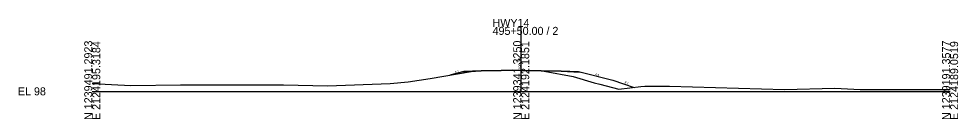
# Model space of a CAD drawing. Extents: x -26 to 303, y -10 to 11521.
# Drawn here: x -25.7 to 302.8, y 6990.3 to 7025.3 of the extents above; entities that cross this region are included whole.
import ezdxf

# ---------------------------------------------------------------- set-up
doc = ezdxf.new("R2010")
doc.units = 0
for name, color, linetype in [('XS_CELL', 7, 'Continuous'), ('XS_P_FINISHED_GRADE', 7, 'Continuous'), ('XS_P_SUBGRADE_GRANULAR', 7, 'Continuous'), ('XS_P_SUBGRADE_LEVELING', 7, 'Continuous'), ('XS_P_TX_FS_BS', 7, 'Continuous'), ('XS_X_GROUND', 7, 'Continuous'), ('XS_X_GROUND_TX', 7, 'Continuous')]:
    doc.layers.add(name, color=color, linetype=linetype)

msp = doc.modelspace()

# ---------------------------------------------------------------- linework, layer by layer
at = {"layer": 'XS_CELL'}
for p, q in [((150, 7000), (150, 7022.48)), ((0, 7000), (150, 7000)), ((150, 7000), (300, 7000))]:
    msp.add_line(p, q, dxfattribs=at)
at = {"layer": 'XS_P_FINISHED_GRADE'}
for p, q in [((130, 7006.87), (125.03, 7005.63)), ((136, 7007.11), (130, 7006.87)), ((150, 7007.39), (136, 7007.11)), ((150, 7007.39), (164, 7007.11)), ((164, 7007.11), (170, 7006.87)), ((170, 7006.87), (182, 7003.87)), ((182, 7003.87), (189.47, 7001.38))]:
    msp.add_line(p, q, dxfattribs=at)
at = {"layer": 'XS_P_SUBGRADE_GRANULAR'}
for p, q in [((136, 7006.99), (129.4, 7006.72)), ((164, 7006.99), (170.6, 7006.72))]:
    msp.add_line(p, q, dxfattribs=at)
at = {"layer": 'XS_P_SUBGRADE_LEVELING'}
for p, q in [((150, 7007.26), (136, 7006.99)), ((136, 7006.99), (136, 7007.11)), ((150, 7007.26), (164, 7006.99)), ((164, 7006.99), (164, 7007.11))]:
    msp.add_line(p, q, dxfattribs=at)
at = {"layer": 'XS_X_GROUND'}
for p, q in [((110.46, 7003.29), (118.22, 7004.45)), ((118.22, 7004.45), (132.52, 7006.92)), ((132.52, 7006.92), (134.03, 7007.05)), ((134.03, 7007.05), (135.18, 7007.14)), ((135.18, 7007.14), (140.16, 7007.29)), ((140.16, 7007.29), (146.88, 7007.49)), ((146.88, 7007.49), (150, 7007.39)), ((150, 7007.39), (157.65, 7007.14)), ((157.65, 7007.14), (157.99, 7007.06)), ((157.99, 7007.06), (168.24, 7005.13)), ((168.24, 7005.13), (175.47, 7003)), ((0, 7002.69), (13.49, 7002.06)), ((13.49, 7002.06), (30.83, 7002.22)), ((30.83, 7002.22), (66.86, 7002.3)), ((66.86, 7002.3), (82.27, 7001.94)), ((82.27, 7001.94), (104.14, 7002.72)), ((104.14, 7002.72), (110.46, 7003.29)), ((175.47, 7003), (177.47, 7002.46)), ((177.47, 7002.46), (184.17, 7000.72)), ((184.17, 7000.72), (191.85, 7001.68)), ((191.85, 7001.68), (193.28, 7001.83)), ((193.28, 7001.83), (201.86, 7001.8)), ((201.86, 7001.8), (242.07, 7000.7)), ((242.07, 7000.7), (259.71, 7001.15)), ((259.71, 7001.15), (268.61, 7000.7)), ((268.61, 7000.7), (287.28, 7000.6)), ((287.28, 7000.6), (300, 7000.6))]:
    msp.add_line(p, q, dxfattribs=at)

# ---------------------------------------------------------------- texts
at = {"layer": 'XS_CELL'}
for s, p in [('HWY14', (140, 7022.48)), ('495+50.00 / 2', (140, 7019.68)), ('EL 98', (-26, 6998.6))]:
    msp.add_text(s, height=2.8, dxfattribs=at).set_placement(p)
for s, p in [('N 1239491.2923', (0, 6990)), ('N 1239341.3250', (150, 6990)), ('N 1239191.3577', (300, 6990)), ('E 2124195.3184', (2.8, 6990)), ('E 2124192.1851', (152.8, 6990)), ('E 2124189.0519', (302.8, 6990))]:
    msp.add_text(s, height=2.8, rotation=90, dxfattribs=at).set_placement(p)
at = {"layer": 'XS_P_TX_FS_BS'}
for s, rotation, p in [('4:1', 14.0362, (126.88, 7006.26)), ('4:1', 345.9638, (175.77, 7005.62)), ('3:1', 341.5651, (186.02, 7002.9))]:
    msp.add_text(s, height=0.8, rotation=rotation, dxfattribs=at).set_placement(p)
at = {"layer": 'XS_X_GROUND_TX'}
msp.add_text('105.39', height=1, rotation=90, dxfattribs=at).set_placement((150, 7007.49))

doc.saveas('drawing.dxf')
